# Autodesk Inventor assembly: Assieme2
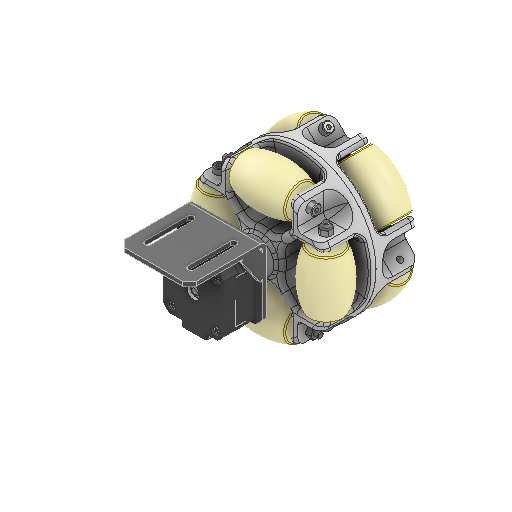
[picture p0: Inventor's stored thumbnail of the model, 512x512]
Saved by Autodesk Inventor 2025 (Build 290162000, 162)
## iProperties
Created: 2025-05
Part Number: Assieme2
Document SubType Name: Assembly
Designer: R5800u
Author: R5800u
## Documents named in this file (9)
- C:\Users\R5800u\Desktop\mecanum4\Assieme2.iam
- C:\Users\R5800u\Desktop\mecanum4\Assieme1.iam
- C:\Users\R5800u\Desktop\mecanum4\vite2.ipt
- C:\Users\R5800u\Documents\Inventor\Content Center Files\R2025\it-IT\ANSI B18.2.4.2M\ANSI B18.2.4.2M - M4x0,7 - 7.ipt
- C:\Users\R5800u\Desktop\mecanum4\Assieme1b.iam
- C:\Users\R5800u\Desktop\mecanum4\ruota.ipt
- C:\Users\R5800u\Documents\Inventor\Content Center Files\R2025\it-IT\AS 1421(2)\AS 1421 - M4 x 12 Punta a coppa.ipt
- C:\Users\R5800u\Desktop\drone\nema17_compatto\nema17_pancake\nema17_pancake.iam
- C:\Users\R5800u\Desktop\drone\NEMA 17 A-Body\NEMA 17 A-Body.ipt
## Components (23 placed, 8 different names)
1. Assieme1b:1 [sub-assembly] — Coincidente:1, Angolo:1, Coincidente:2, Rotazionale:1, Coincidente:4, Coincidente:6, Rotazionale:3, Coincidente:8, Coincidente:9
2. Assieme1:2 [sub-assembly] — Coincidente:1, Angolo:1, Coincidente:2, Rotazionale:2
3. vite2:5 — Rotazionale:2, Coincidente:7
4. ANSI B18.2.4.2M M4x0,7:5
5. AS 1421 Punta a coppa - Metrico M4 x 12 Punta a coppa:1 — Rotazionale:3
6. nema17_pancake:1 [sub-assembly] — Coincidente:8, Coincidente:9, Coincidente:10
7. NEMA 17 A-Body:1 — Coincidente:10
8. ANSI B18.2.4.2M M4x0,7:1 — Coincidente:4
9. vite2:1 — Rotazionale:1, Coincidente:5
10. ANSI B18.2.4.2M M4x0,7:2
11. vite2:2
12. ANSI B18.2.4.2M M4x0,7:3
13. vite2:3
14. ANSI B18.2.4.2M M4x0,7:4
15. vite2:4
16. ruota:1 — Coincidente:5, Coincidente:6
17. ruota:2
18. ruota:3
19. ruota:4
20. ruota:5 — Coincidente:7
21. ruota:6
22. ruota:7
23. ruota:8
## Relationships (13: Mate 9, RevoluteJoint 3, Angle 1)
- Coincidente:1 [Mate]: Assieme1b:1 ↔ Assieme1:2
- Angolo:1 [Angle]: Assieme1b:1 ↔ Assieme1:2
- Coincidente:2 [Mate]: Assieme1b:1 ↔ Assieme1:2
- Rotazionale:1 [RevoluteJoint]: Assieme1b:1 ↔ vite2:1
- Coincidente:4 [Mate]: Assieme1b:1 ↔ ANSI B18.2.4.2M M4x0,7:1
- Coincidente:5 [Mate]: vite2:1 ↔ ruota:1
- Coincidente:6 [Mate]: Assieme1b:1 ↔ ruota:1
- Rotazionale:2 [RevoluteJoint]: Assieme1:2 ↔ vite2:5
- Coincidente:7 [Mate]: vite2:5 ↔ ruota:5
- Rotazionale:3 [RevoluteJoint]: Assieme1b:1 ↔ AS 1421 Punta a coppa - Metrico M4 x 12 Punta a coppa:1
- Coincidente:8 [Mate]: Assieme1b:1 ↔ nema17_pancake:1
- Coincidente:9 [Mate]: Assieme1b:1 ↔ nema17_pancake:1
- Coincidente:10 [Mate]: nema17_pancake:1 ↔ NEMA 17 A-Body:1
